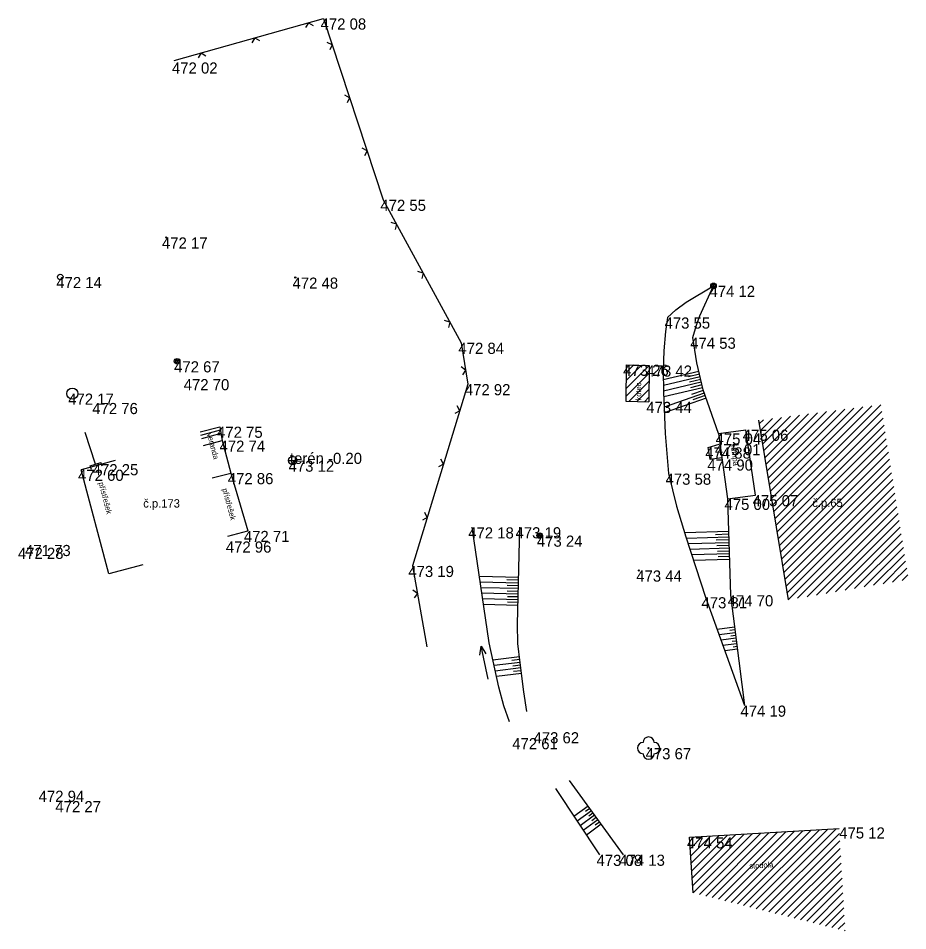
# Model space of a CAD drawing. Extents: x -553731 to -553573, y -1076100 to -1075378.
# Drawn here: x -553652.8 to -553573, y -1075951.9 to -1075870 of the extents above; entities that cross this region are included whole.
import ezdxf

# ---------------------------------------------------------------- set-up
doc = ezdxf.new("R2010")
doc.units = 0
for name, color, linetype in [('1', 7, 'Continuous'), ('12', 7, 'Continuous'), ('14', 7, 'Continuous'), ('18', 7, 'Continuous'), ('20', 7, 'Continuous'), ('26', 7, 'Continuous'), ('27', 7, 'Continuous'), ('28', 7, 'Continuous'), ('32', 7, 'Continuous'), ('34', 7, 'Continuous'), ('40', 7, 'Continuous'), ('52', 7, 'Continuous'), ('54', 7, 'Continuous'), ('6', 7, 'Continuous')]:
    doc.layers.add(name, color=color, linetype=linetype)

# ---------------------------------------------------------------- blocks, each defined once
blk = doc.blocks.new('POINT_DISPLAY')
blk.add_line((0, 0), (0, 0))
blk = doc.blocks.new('ST')
at = {"layer": '1'}
blk.add_line((-0.375, 0), (0.375, 0), dxfattribs=at)
blk.add_circle((0, 0), 0.375, dxfattribs=at)
blk = doc.blocks.new('SLB')
at = {"layer": '20'}
for radius in [0.25, 0.158, 0.05]:
    blk.add_circle((0, 0), radius, dxfattribs=at)
blk = doc.blocks.new('SAK')
at = {"layer": '40'}
blk.add_circle((0, 0), 0.5, dxfattribs=at)
blk = doc.blocks.new('SV')
at = {"layer": '1'}
blk.add_circle((0, 0), 0.25, dxfattribs=at)
blk = doc.blocks.new('T')
at = {"layer": '6'}
blk.add_circle((0, 0), 0.05, dxfattribs=at)
blk = doc.blocks.new('SLDP')
at = {"layer": '20'}
for radius in [0.25, 0.158, 0.05]:
    blk.add_circle((0, 0), radius, dxfattribs=at)
blk = doc.blocks.new('STL')
at = {"layer": '34'}
blk.add_circle((0, 0), 0.05, dxfattribs=at)
for centre, start, end in [((0, 0.5), 0, 180), ((-0.5, 0), 90, 270), ((0.5, 0), 270, 90), ((0, -0.5), 180, 0)]:
    blk.add_arc(centre, 0.5, start, end, dxfattribs=at)
blk = doc.blocks.new('VYUST')
at = {"layer": '40'}
for p, q in [((-0.35, 0.5), (0, 0.5)), ((0, 0.5), (0, -0.5)), ((0, 0), (3, 0)), ((-0.351, -0.5), (0, -0.5))]:
    blk.add_line(p, q, dxfattribs=at)
blk = doc.blocks.new('VOTOK')
at = {"layer": '28'}
for p, q in [((-3.001, 0.001), (0, 0)), ((-0.751, 0.282), (0, 0)), ((0, 0), (-0.751, -0.281))]:
    blk.add_line(p, q, dxfattribs=at)

msp = doc.modelspace()

# ---------------------------------------------------------------- linework, layer by layer
at = {"layer": '12'}
for p, q in [((-553638.84, -1075873.8), (-553625.45, -1075870.02)), ((-553626.81, -1075870.404), (-553627.055, -1075870.841)), ((-553626.81, -1075870.404), (-553626.373, -1075870.648)), ((-553625.45, -1075870.02), (-553620.09, -1075886.29)), ((-553631.622, -1075871.762), (-553631.867, -1075872.199)), ((-553631.622, -1075871.762), (-553631.185, -1075872.007)), ((-553624.668, -1075872.394), (-553625.115, -1075872.169)), ((-553624.668, -1075872.394), (-553624.893, -1075872.841)), ((-553636.434, -1075873.121), (-553636.679, -1075873.558)), ((-553636.434, -1075873.121), (-553635.997, -1075873.365)), ((-553623.103, -1075877.143), (-553623.55, -1075876.918)), ((-553623.103, -1075877.143), (-553623.329, -1075877.59)), ((-553621.539, -1075881.892), (-553621.986, -1075881.667)), ((-553621.539, -1075881.892), (-553621.764, -1075882.339)), ((-553620.09, -1075886.29), (-553613.1, -1075899.12)), ((-553618.894, -1075888.485), (-553619.374, -1075888.344)), ((-553618.894, -1075888.485), (-553619.035, -1075888.966)), ((-553616.502, -1075892.876), (-553616.982, -1075892.734)), ((-553616.502, -1075892.876), (-553616.643, -1075893.356)), ((-553614.11, -1075897.267), (-553614.59, -1075897.125)), ((-553614.11, -1075897.267), (-553614.251, -1075897.747)), ((-553613.1, -1075899.12), (-553612.5, -1075902.83)), ((-553612.701, -1075901.588), (-553613.107, -1075901.295)), ((-553612.701, -1075901.588), (-553612.994, -1075901.994)), ((-553612.5, -1075902.83), (-553617.46, -1075919.14)), ((-553613.227, -1075905.222), (-553613.463, -1075904.78)), ((-553613.227, -1075905.222), (-553613.669, -1075905.458)), ((-553614.682, -1075910.006), (-553614.918, -1075909.564)), ((-553614.682, -1075910.006), (-553615.124, -1075910.241)), ((-553616.137, -1075914.789), (-553616.373, -1075914.348)), ((-553616.137, -1075914.789), (-553616.579, -1075915.025)), ((-553617.46, -1075919.14), (-553616.19, -1075926.4)), ((-553617.029, -1075921.603), (-553617.439, -1075921.315)), ((-553617.029, -1075921.603), (-553617.317, -1075922.012))]:
    msp.add_line(p, q, dxfattribs=at)
at = {"layer": '14'}
for p, q in [((-553598.3, -1075901.09), (-553598.32, -1075904.35)), ((-553598.3, -1075901.09), (-553596.24, -1075901.16)), ((-553596.24, -1075901.16), (-553596.26, -1075904.42)), ((-553598.32, -1075904.35), (-553596.26, -1075904.42)), ((-553586.427, -1075906.078), (-553583.78, -1075922.191)), ((-553636.199, -1075908.345), (-553634.53, -1075907.9)), ((-553634.53, -1075907.9), (-553633.76, -1075910.81)), ((-553644.142, -1075909.697), (-553647.19, -1075910.51)), ((-553644.698, -1075919.853), (-553647.19, -1075910.51)), ((-553635.423, -1075911.254), (-553633.76, -1075910.81)), ((-553633.76, -1075910.81), (-553632.23, -1075916)), ((-553634.029, -1075916.48), (-553632.23, -1075916)), ((-553641.65, -1075919.04), (-553644.698, -1075919.853)), ((-553592.61, -1075943.49), (-553579.206, -1075942.707)), ((-553592.288, -1075948.48), (-553592.61, -1075943.49))]:
    msp.add_line(p, q, dxfattribs=at)
at = {"layer": '18'}
for p, q in [((-553636.524, -1075907.126), (-553634.74, -1075906.65)), ((-553636.447, -1075907.415), (-553634.69, -1075906.947)), ((-553636.369, -1075907.705), (-553634.64, -1075907.244)), ((-553634.74, -1075906.65), (-553634.53, -1075907.9)), ((-553590.03, -1075907.25), (-553587.57, -1075906.92)), ((-553590.03, -1075907.25), (-553589.22, -1075913.12)), ((-553586.7, -1075912.79), (-553587.57, -1075906.92)), ((-553590.96, -1075908.51), (-553589.97, -1075908.21)), ((-553590.76, -1075909.59), (-553590.96, -1075908.51)), ((-553589.727, -1075909.447), (-553590.76, -1075909.59)), ((-553589.22, -1075913.12), (-553586.7, -1075912.79))]:
    msp.add_line(p, q, dxfattribs=at)
at = {"layer": '26'}
for p, q in [((-553591.792, -1075901.692), (-553594.969, -1075902.446)), ((-553591.676, -1075902.179), (-553594.96, -1075902.959)), ((-553591.734, -1075901.936), (-553592.703, -1075902.166)), ((-553591.561, -1075902.665), (-553594.951, -1075903.47)), ((-553591.445, -1075903.152), (-553594.934, -1075903.98)), ((-553591.619, -1075902.422), (-553592.62, -1075902.66)), ((-553591.503, -1075902.909), (-553592.535, -1075903.154)), ((-553591.298, -1075903.629), (-553594.9, -1075904.891)), ((-553591.381, -1075903.393), (-553592.44, -1075903.764)), ((-553591.216, -1075903.865), (-553592.318, -1075904.251)), ((-553591.133, -1075904.101), (-553594.88, -1075905.413)), ((-553589.128, -1075916.057), (-553593.053, -1075916.179)), ((-553589.113, -1075916.557), (-553592.9, -1075916.675)), ((-553589.097, -1075917.057), (-553592.738, -1075917.171)), ((-553589.121, -1075916.307), (-553590.278, -1075916.343)), ((-553589.105, -1075916.807), (-553590.219, -1075916.842)), ((-553589.082, -1075917.556), (-553592.577, -1075917.665)), ((-553589.089, -1075917.307), (-553590.16, -1075917.34)), ((-553589.074, -1075917.806), (-553590.1, -1075917.838)), ((-553589.066, -1075918.056), (-553592.416, -1075918.161)), ((-553589.05, -1075918.556), (-553592.254, -1075918.656)), ((-553589.058, -1075918.306), (-553590.041, -1075918.337)), ((-553607.951, -1075920.18), (-553611.459, -1075920.094)), ((-553607.963, -1075920.68), (-553611.387, -1075920.596)), ((-553607.975, -1075921.179), (-553611.314, -1075921.097)), ((-553607.957, -1075920.43), (-553608.997, -1075920.404)), ((-553607.969, -1075920.93), (-553608.984, -1075920.905)), ((-553607.988, -1075921.679), (-553611.241, -1075921.599)), ((-553607.982, -1075921.429), (-553608.97, -1075921.405)), ((-553607.994, -1075921.929), (-553608.957, -1075921.905)), ((-553608, -1075922.179), (-553611.168, -1075922.101)), ((-553608.012, -1075922.679), (-553611.095, -1075922.603)), ((-553608.006, -1075922.429), (-553608.944, -1075922.406)), ((-553588.582, -1075924.639), (-553590.14, -1075924.839)), ((-553588.518, -1075925.135), (-553589.966, -1075925.321)), ((-553588.55, -1075924.887), (-553589.001, -1075924.945)), ((-553588.455, -1075925.631), (-553589.793, -1075925.803)), ((-553588.486, -1075925.383), (-553588.904, -1075925.437)), ((-553588.423, -1075925.879), (-553588.808, -1075925.929)), ((-553588.391, -1075926.127), (-553589.619, -1075926.285)), ((-553588.327, -1075926.623), (-553589.446, -1075926.766)), ((-553588.359, -1075926.375), (-553588.711, -1075926.42)), ((-553607.876, -1075927.303), (-553610.262, -1075927.585)), ((-553607.846, -1075927.551), (-553608.555, -1075927.635)), ((-553607.817, -1075927.8), (-553610.156, -1075928.076)), ((-553607.755, -1075928.296), (-553610.046, -1075928.582)), ((-553607.786, -1075928.048), (-553608.48, -1075928.134)), ((-553607.724, -1075928.544), (-553608.405, -1075928.629)), ((-553607.693, -1075928.792), (-553609.94, -1075929.072)), ((-553601.72, -1075940.708), (-553602.983, -1075941.627)), ((-553601.426, -1075941.112), (-553602.706, -1075942.044)), ((-553601.132, -1075941.517), (-553602.429, -1075942.461)), ((-553601.573, -1075940.91), (-553601.954, -1075941.188)), ((-553601.279, -1075941.314), (-553601.665, -1075941.596)), ((-553600.837, -1075941.921), (-553602.151, -1075942.878)), ((-553600.543, -1075942.325), (-553601.874, -1075943.294)), ((-553600.985, -1075941.719), (-553601.376, -1075942.004)), ((-553600.69, -1075942.123), (-553601.087, -1075942.412))]:
    msp.add_line(p, q, dxfattribs=at)
at = {"layer": '27'}
for p, q in [((-553589.22, -1075913.12), (-553588.95, -1075921.77)), ((-553591.18, -1075921.95), (-553587.68, -1075931.67)), ((-553588.95, -1075921.77), (-553587.68, -1075931.67)), ((-553603.4, -1075938.4), (-553598.56, -1075945.05))]:
    msp.add_line(p, q, dxfattribs=at)
for points in [[(-553594.6, -1075896.85), (-553593.851, -1075896.177), (-553592.905, -1075895.487), (-553590.47, -1075894.01)], [(-553592.31, -1075898.66), (-553592.002, -1075897.551), (-553591.691, -1075896.712), (-553590.47, -1075894.01)], [(-553594.6, -1075896.85), (-553594.777, -1075898.11), (-553594.922, -1075899.85), (-553594.984, -1075901.576), (-553594.95, -1075903.551), (-553594.811, -1075907.251), (-553594.51, -1075910.86)], [(-553590.03, -1075907.25), (-553591.403, -1075903.33), (-553591.978, -1075900.908), (-553592.31, -1075898.66)], [(-553594.51, -1075910.86), (-553593.776, -1075913.769), (-553592.947, -1075916.531), (-553591.18, -1075921.95)], [(-553607.2, -1075932.21), (-553607.489, -1075930.432), (-553607.814, -1075927.825), (-553608.016, -1075926.114), (-553608.054, -1075924.372), (-553607.84, -1075915.67)]]:
    msp.add_lwpolyline(points, dxfattribs=at)
at = {"layer": '28'}
msp.add_line((-553604.65, -1075939.12), (-553600.7, -1075945.06), dxfattribs=at)
msp.add_lwpolyline([(-553608.77, -1075933.13), (-553609.263, -1075931.703), (-553609.732, -1075930.031), (-553610.595, -1075926.051), (-553612.1, -1075915.68)], dxfattribs=at)
at = {"layer": '32'}
for p, q in [((-553598.313, -1075903.224), (-553596.248, -1075901.16)), ((-553598.309, -1075902.513), (-553596.932, -1075901.136)), ((-553598.304, -1075901.801), (-553597.616, -1075901.113)), ((-553598.317, -1075903.936), (-553596.244, -1075901.863)), ((-553598.034, -1075904.36), (-553596.249, -1075902.574)), ((-553597.35, -1075904.383), (-553596.253, -1075903.286)), ((-553596.666, -1075904.406), (-553596.257, -1075903.997)), ((-553585.177, -1075913.689), (-553576.267, -1075904.779)), ((-553585.077, -1075914.296), (-553575.456, -1075904.675)), ((-553585.975, -1075908.83), (-553582.753, -1075905.608)), ((-553585.875, -1075909.437), (-553581.942, -1075905.504)), ((-553585.775, -1075910.045), (-553581.132, -1075905.401)), ((-553585.676, -1075910.652), (-553580.321, -1075905.297)), ((-553585.576, -1075911.259), (-553579.51, -1075905.193)), ((-553585.476, -1075911.867), (-553578.699, -1075905.09)), ((-553585.376, -1075912.474), (-553577.888, -1075904.986)), ((-553585.277, -1075913.081), (-553577.078, -1075904.882)), ((-553584.977, -1075914.903), (-553575.36, -1075905.286)), ((-553586.374, -1075906.401), (-553585.996, -1075906.023)), ((-553586.274, -1075907.008), (-553585.186, -1075905.919)), ((-553586.174, -1075907.615), (-553584.375, -1075905.816)), ((-553586.075, -1075908.223), (-553583.564, -1075905.712)), ((-553584.877, -1075915.511), (-553575.263, -1075905.896)), ((-553584.778, -1075916.118), (-553575.167, -1075906.507)), ((-553584.678, -1075916.725), (-553575.07, -1075907.118)), ((-553584.578, -1075917.333), (-553574.974, -1075907.728)), ((-553584.478, -1075917.94), (-553574.877, -1075908.339)), ((-553584.379, -1075918.547), (-553574.781, -1075908.95)), ((-553584.279, -1075919.155), (-553574.684, -1075909.56)), ((-553584.179, -1075919.762), (-553574.588, -1075910.171)), ((-553584.079, -1075920.369), (-553574.491, -1075910.782)), ((-553583.979, -1075920.977), (-553574.395, -1075911.392)), ((-553583.88, -1075921.584), (-553574.299, -1075912.003)), ((-553583.78, -1075922.191), (-553574.202, -1075912.614)), ((-553582.927, -1075922.046), (-553574.106, -1075913.224)), ((-553582.075, -1075921.901), (-553574.009, -1075913.835)), ((-553581.223, -1075921.755), (-553573.913, -1075914.445)), ((-553580.37, -1075921.61), (-553573.816, -1075915.056)), ((-553579.518, -1075921.465), (-553573.72, -1075915.667)), ((-553578.666, -1075921.32), (-553573.623, -1075916.277)), ((-553577.813, -1075921.174), (-553573.527, -1075916.888)), ((-553576.961, -1075921.029), (-553573.431, -1075917.499)), ((-553576.109, -1075920.884), (-553573.334, -1075918.109)), ((-553575.256, -1075920.739), (-553573.238, -1075918.72)), ((-553574.404, -1075920.594), (-553573.141, -1075919.331)), ((-553573.552, -1075920.448), (-553573.045, -1075919.941)), ((-553592.374, -1075947.152), (-553588.47, -1075943.248)), ((-553592.331, -1075947.816), (-553587.719, -1075943.204)), ((-553592.288, -1075948.48), (-553586.968, -1075943.16)), ((-553591.722, -1075948.621), (-553586.217, -1075943.117)), ((-553591.157, -1075948.763), (-553585.466, -1075943.073)), ((-553590.591, -1075948.904), (-553584.716, -1075943.029)), ((-553590.025, -1075949.046), (-553583.965, -1075942.985)), ((-553589.46, -1075949.187), (-553583.214, -1075942.941)), ((-553588.894, -1075949.329), (-553582.463, -1075942.897)), ((-553588.329, -1075949.47), (-553581.712, -1075942.853)), ((-553587.763, -1075949.612), (-553580.961, -1075942.809)), ((-553587.197, -1075949.753), (-553580.21, -1075942.766)), ((-553586.632, -1075949.895), (-553579.459, -1075942.722)), ((-553586.066, -1075950.036), (-553579.18, -1075943.15)), ((-553592.588, -1075943.83), (-553592.225, -1075943.468)), ((-553592.545, -1075944.495), (-553591.474, -1075943.424)), ((-553592.502, -1075945.159), (-553590.723, -1075943.38)), ((-553592.459, -1075945.823), (-553589.972, -1075943.336)), ((-553592.417, -1075946.487), (-553589.221, -1075943.292)), ((-553585.5, -1075950.178), (-553579.14, -1075943.817)), ((-553584.935, -1075950.319), (-553579.1, -1075944.484)), ((-553584.369, -1075950.461), (-553579.06, -1075945.152)), ((-553583.803, -1075950.602), (-553579.02, -1075945.819)), ((-553583.238, -1075950.744), (-553578.98, -1075946.486)), ((-553582.672, -1075950.885), (-553578.941, -1075947.153)), ((-553582.107, -1075951.026), (-553578.901, -1075947.821)), ((-553581.541, -1075951.168), (-553578.861, -1075948.488)), ((-553580.975, -1075951.309), (-553578.821, -1075949.155)), ((-553580.41, -1075951.451), (-553578.781, -1075949.823)), ((-553579.844, -1075951.592), (-553578.742, -1075950.49)), ((-553579.278, -1075951.734), (-553578.702, -1075951.157)), ((-553578.713, -1075951.875), (-553578.662, -1075951.824))]:
    msp.add_line(p, q, dxfattribs=at)

# ---------------------------------------------------------------- block references
at = {"layer": '1'}
for name, p in [('POINT_DISPLAY', (-553625.45, -1075870.02)), ('POINT_DISPLAY', (-553638.78, -1075873.97)), ('POINT_DISPLAY', (-553620.09, -1075886.29)), ('POINT_DISPLAY', (-553639.57, -1075889.67)), ('SV', (-553649.06, -1075893.22)), ('POINT_DISPLAY', (-553649.06, -1075893.22)), ('POINT_DISPLAY', (-553627.98, -1075893.27)), ('POINT_DISPLAY', (-553590.47, -1075894.01)), ('POINT_DISPLAY', (-553594.6, -1075896.85)), ('POINT_DISPLAY', (-553592.31, -1075898.66)), ('POINT_DISPLAY', (-553613.1, -1075899.12)), ('POINT_DISPLAY', (-553638.58, -1075900.78)), ('POINT_DISPLAY', (-553598.3, -1075901.09)), ('POINT_DISPLAY', (-553596.24, -1075901.16)), ('POINT_DISPLAY', (-553637.73, -1075902.38)), ('POINT_DISPLAY', (-553612.5, -1075902.83)), ('POINT_DISPLAY', (-553647.98, -1075903.68)), ('POINT_DISPLAY', (-553645.92, -1075904.52)), ('POINT_DISPLAY', (-553596.26, -1075904.42)), ('POINT_DISPLAY', (-553634.74, -1075906.65)), ('POINT_DISPLAY', (-553590.03, -1075907.25)), ('POINT_DISPLAY', (-553587.57, -1075906.92)), ('POINT_DISPLAY', (-553634.53, -1075907.9)), ('POINT_DISPLAY', (-553590.96, -1075908.51)), ('POINT_DISPLAY', (-553589.97, -1075908.21)), ('ST', (-553628.21, -1075909.69)), ('POINT_DISPLAY', (-553628.21, -1075909.69)), ('POINT_DISPLAY', (-553590.76, -1075909.59)), ('POINT_DISPLAY', (-553647.19, -1075910.51)), ('POINT_DISPLAY', (-553645.89, -1075910.01)), ('POINT_DISPLAY', (-553633.76, -1075910.81)), ('POINT_DISPLAY', (-553594.51, -1075910.86)), ('POINT_DISPLAY', (-553586.7, -1075912.79)), ('POINT_DISPLAY', (-553589.22, -1075913.12)), ('POINT_DISPLAY', (-553632.23, -1075916)), ('POINT_DISPLAY', (-553612.1, -1075915.68)), ('POINT_DISPLAY', (-553607.84, -1075915.67)), ('POINT_DISPLAY', (-553633.93, -1075916.95)), ('POINT_DISPLAY', (-553606.06, -1075916.42)), ('POINT_DISPLAY', (-553652.6, -1075917.51)), ('POINT_DISPLAY', (-553651.85, -1075917.26)), ('POINT_DISPLAY', (-553617.46, -1075919.14)), ('POINT_DISPLAY', (-553597.16, -1075919.55)), ('POINT_DISPLAY', (-553591.18, -1075921.95)), ('POINT_DISPLAY', (-553588.95, -1075921.77)), ('POINT_DISPLAY', (-553587.68, -1075931.67)), ('POINT_DISPLAY', (-553606.34, -1075934.06)), ('POINT_DISPLAY', (-553608.14, -1075934.59)), ('POINT_DISPLAY', (-553596.29, -1075935.49)), ('POINT_DISPLAY', (-553650.74, -1075939.31)), ('POINT_DISPLAY', (-553649.24, -1075940.24)), ('POINT_DISPLAY', (-553578.82, -1075942.6)), ('POINT_DISPLAY', (-553592.61, -1075943.49)), ('POINT_DISPLAY', (-553600.7, -1075945.06)), ('POINT_DISPLAY', (-553598.56, -1075945.05))]:
    msp.add_blockref(name, p, dxfattribs=at)
at = {"layer": '20'}
for name, p in [('SLDP', (-553590.47, -1075894.01)), ('SLB', (-553638.58, -1075900.78)), ('SLDP', (-553606.06, -1075916.42))]:
    msp.add_blockref(name, p, dxfattribs=at)
at = {"layer": '28', "xscale": 0.9999992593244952, "yscale": 0.9999992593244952, "rotation": 102.34429196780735}
msp.add_blockref('VOTOK', (-553611.313, -1075926.357), dxfattribs=at)
at = {"layer": '32'}
for p in [(-553598.3, -1075901.09), (-553575.456, -1075904.675), (-553592.288, -1075948.48)]:
    msp.add_blockref('POINT_DISPLAY', p, dxfattribs=at)
at = {"layer": '34'}
msp.add_blockref('STL', (-553596.29, -1075935.49), dxfattribs=at)
at = {"layer": '40'}
msp.add_blockref('SAK', (-553647.98, -1075903.68), dxfattribs=at)
at = {"layer": '40', "xscale": 0.9999984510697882, "yscale": 0.9999984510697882, "rotation": 108.27185909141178}
msp.add_blockref('VYUST', (-553645.89, -1075910.01), dxfattribs=at)
at = {"layer": '6'}
for p in [(-553639.57, -1075889.67), (-553627.98, -1075893.27), (-553597.16, -1075919.55)]:
    msp.add_blockref('T', p, dxfattribs=at)

# ---------------------------------------------------------------- texts
at = {"layer": '52'}
for s, rotation, p in [('kotec', 90, (-553596.952, -1075904.295)), ('veranda', 284.93629, (-553635.918, -1075907.29)), ('žumpa', 277.85662, (-553588.949, -1075908.194)), ('přístřešek', 284.93447, (-553645.645, -1075911.698)), ('přístřešek', 284.93447, (-553634.536, -1075912.25)), ('stodola', 3.68955, (-553587.237, -1075946.317))]:
    msp.add_text(s, height=0.5, rotation=rotation, dxfattribs=at).set_placement(p)
at = {"layer": '54'}
for s, p in [('č.p.173', (-553641.617, -1075913.907)), ('č.p.65', (-553581.607, -1075913.852))]:
    msp.add_text(s, height=0.75, dxfattribs=at).set_placement(p)
at = {"layer": '6'}
for s, p in [('472 08 ', (-553625.712, -1075871.02)), ('472 02 ', (-553639.042, -1075874.97)), ('472 55 ', (-553620.35, -1075887.29)), ('472 17 ', (-553639.937, -1075890.67)), ('472 14 ', (-553649.417, -1075894.22)), ('472 48 ', (-553628.228, -1075894.27)), ('474 12 ', (-553590.827, -1075895.01)), ('473 55 ', (-553594.86, -1075897.85)), ('474 53 ', (-553592.558, -1075899.66)), ('472 84 ', (-553613.348, -1075900.12)), ('472 67 ', (-553638.85, -1075901.78)), ('473 26 ', (-553598.572, -1075902.09)), ('473 42 ', (-553596.488, -1075902.16)), ('472 70 ', (-553637.99, -1075903.38)), ('472 92 ', (-553612.772, -1075903.83)), ('472 17 ', (-553648.347, -1075904.68)), ('472 76 ', (-553646.19, -1075905.52)), ('473 44 ', (-553596.496, -1075905.42)), ('472 75 ', (-553634.998, -1075907.65)), ('475 04 ', (-553590.28, -1075908.25)), ('475 06 ', (-553587.844, -1075907.92)), ('472 74 ', (-553634.776, -1075908.9)), ('474 88 ', (-553591.208, -1075909.51)), ('475 01 ', (-553590.339, -1075909.21)), ('473 12 ', (-553628.579, -1075910.69)), ('terén -0.20', (-553628.464, -1075909.99)), ('474 90 ', (-553591.022, -1075910.59)), ('472 60 ', (-553647.464, -1075911.51)), ('472 25 ', (-553646.15, -1075911.01)), ('472 86 ', (-553634.032, -1075911.81)), ('473 58 ', (-553594.77, -1075911.86)), ('475 07 ', (-553586.96, -1075913.79)), ('475 00 ', (-553589.484, -1075914.12)), ('472 71 ', (-553632.595, -1075917)), ('472 18 ', (-553612.469, -1075916.68)), ('473 19 ', (-553608.221, -1075916.67)), ('472 96 ', (-553634.214, -1075917.95)), ('473 24 ', (-553606.308, -1075917.42)), ('472 28 ', (-553652.86, -1075918.51)), ('471 73 ', (-553652.217, -1075918.26)), ('473 19 ', (-553617.841, -1075920.14)), ('473 44 ', (-553597.396, -1075920.55)), ('473 81 ', (-553591.547, -1075922.95)), ('474 70 ', (-553589.198, -1075922.77)), ('474 19 ', (-553588.049, -1075932.67)), ('473 62 ', (-553606.612, -1075935.06)), ('472 61 ', (-553608.519, -1075935.59)), ('473 67 ', (-553596.56, -1075936.49)), ('472 94 ', (-553651, -1075940.31)), ('472 27 ', (-553649.498, -1075941.24)), ('475 12 ', (-553579.189, -1075943.6)), ('474 54 ', (-553592.846, -1075944.49)), ('473 08 ', (-553600.962, -1075946.06)), ('474 13 ', (-553598.917, -1075946.05))]:
    msp.add_text(s, height=1, dxfattribs=at).set_placement(p)

doc.saveas('drawing.dxf')
